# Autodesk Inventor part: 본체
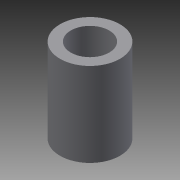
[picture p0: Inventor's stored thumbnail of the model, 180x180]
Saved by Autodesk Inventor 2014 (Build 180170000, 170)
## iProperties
Created: 2015-11
Part Number: 본체
Material: 일반
Document SubType Name: Modeling
Designer: 3sil_66666
Density: 1 g/cm^3
Appearance: 기본값
Author: 3sil_66666
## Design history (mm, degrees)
sketch "스케치1"
  geometry: C1 r 25 at (0, 0); C2 r 16 at (0, 0); C3 r 14 at (0, 0); 1 further point
  constraints: 3 centre point, 3 coincident
  dimensions: "d0" = 50 diameter of C1; "d1" = 32 diameter of C2; "d2" = 28 diameter of C3
extrude "돌출1" new body sketch "스케치1" distance "d3" = 70; taper "d4" = 0 deg
node "솔리드1"
